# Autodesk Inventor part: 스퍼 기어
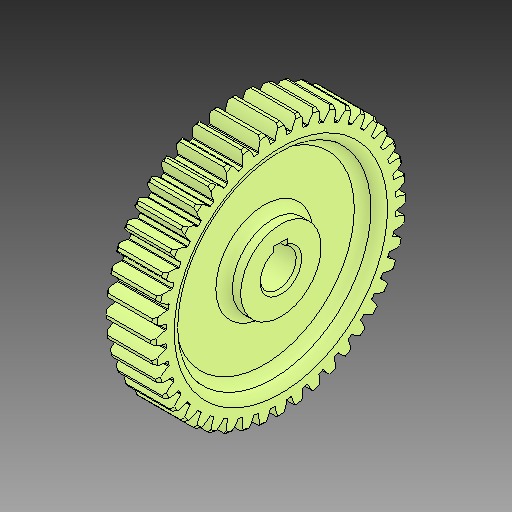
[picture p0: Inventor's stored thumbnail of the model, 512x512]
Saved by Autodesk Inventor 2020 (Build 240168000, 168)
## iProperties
Created: 2024-08
Part Number: 스퍼 기어
Material: 강철, 탄소
Document SubType Name: Modeling
Designer: 1강의실14
Density: 7.85 g/cm^3
Appearance: 기본값
Author: jhkim
Sending System: Autodesk Inventor 2025
Preprocessor: ST-DEVELOPER v20
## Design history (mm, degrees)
feature "솔리드1"
node "솔리드2"
